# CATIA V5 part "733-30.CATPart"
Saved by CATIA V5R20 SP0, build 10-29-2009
Part number: 733-30
Bounding box of the stored display mesh (mm): x -28 to 28, y -28 to 28, z -30 to 63
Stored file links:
  C:\Users\Utente\Desktop\IO LAVORO\3D X SITO CF\X SITO\733\733-30.CATPart
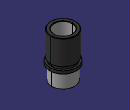
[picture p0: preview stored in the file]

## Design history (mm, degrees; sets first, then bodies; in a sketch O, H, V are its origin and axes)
Set1
  DatumSurface1 to DatumSurface25 "733-30"
Body1 (main body)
